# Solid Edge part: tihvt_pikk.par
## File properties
Author: Argo
Template: Normal.par
Last saved by: Argo
Revision: 9
Application: Solid Edge
Material: Aluminum, 3004
Face Style: Aluminum
Fill Style: ANSI38(Aluminum)
Virtual Style: Polished aluminum
Coef. of Thermal Exp: 2.3e-05
Thermal Conductivity: 170.0
Specific Heat: 920.0
Modulus of Elasticity: 68947570000.0
Poission's Ratio: 0.33
Yield Stress: 68947570.0
Ultimate Stress: 179263682.0
Elongation: 0.0
Density: 2712,000 kg/m^3
Accuracy: 0,990
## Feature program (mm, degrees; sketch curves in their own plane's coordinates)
sketch for "unnamed Protrusion 1" plane through (0, 0, 0) normal (0, 0, 1) x-axis (1, 0, 0)
  circle centre (0, 0) radius 1.5
extrude "unnamed Protrusion 1" add finite 1 along +normal
sketch for "ExtrudedProtrusion_2" plane through (0, 0, 0) normal (0, 0, -1) x-axis (1, 0, 0)
  circle centre (0, 0) radius 1
extrude "ExtrudedProtrusion_2" add finite 8 along +normal
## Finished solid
Body 1: solid body, 5 faces, 4 edges, 0 vertices.
  Faces by surface: plane 3, cylinder 2
  Edges by curve: circle 4
Bounding box of the edges (mm): 3.000 x 3.000 x 9.000, from (-1.5, -1.5, -8) to (1.5, 1.5, 1).
Cylindrical faces by radius (mm): R1 x1, R1.5 x1
Planar faces by outward normal: +z 1, -z 2
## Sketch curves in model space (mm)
circle centre (0, 0, 0) radius 1
circle centre (0, 0, 0) radius 1.5
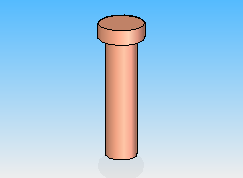
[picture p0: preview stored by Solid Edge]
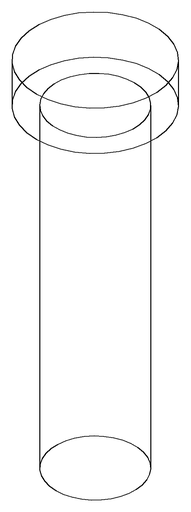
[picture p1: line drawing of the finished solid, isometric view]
